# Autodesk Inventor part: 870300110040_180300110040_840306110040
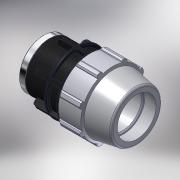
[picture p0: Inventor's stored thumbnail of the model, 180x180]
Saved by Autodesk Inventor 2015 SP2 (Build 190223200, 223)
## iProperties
Created: 2017-02
Part Number: 870300110040_180300110040_840306110040
Material: PVC-Piping
Description: PLASSON FEMALE ADAPTOR 110-4"
Document SubType Name: Modeling
Designer: KIM
Mass: 92.6774 g
Surface Area: 199.44 cm^2
Volume: 66.1981 cm^3
Density: 1.4 g/cm^3
Appearance: PTFE
Author: KIM
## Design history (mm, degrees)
derived "87030.ipt"
feature "Solid1::87030.ipt"
tag "TaggingFeature1"
body "Solid1"
other parameters: "d4" = 39, "d5" = 68.25, "d7" = 181, "d9" = 39, "d11" = 7.8, "d12" = 144.8, "d13" = 120 deg, "d14" = 143, "d15" = 8 deg, "d16" = 162.9, "d18" = 5.5, "d19" = 35 deg, "d20" = 17.5 deg, "d21" = 168.33, "d23" = 0, "d25" = 360 deg, "d27" = 3.62, "d34" = 9.05, "d35" = 81.9, "d36" = 0, "d42" = 68.25, "d43" = 5.43, "d46" = 3.3, "d49" = 215, "d51" = 273, "d53" = 2.2, "d55" = 360 deg, "d61" = 52, "d62" = 88, "d63" = 110.072, "d64" = 91, "d65" = 9.05, "d69" = 130.32, "d70" = 4.525, "d71" = 12.6, "d72" = 0.5, "d73" = 1, "E_" = 181, "H_" = 273, "l_" = 215, "l_2" = 52, "Rp_Rc_" = 110.072
